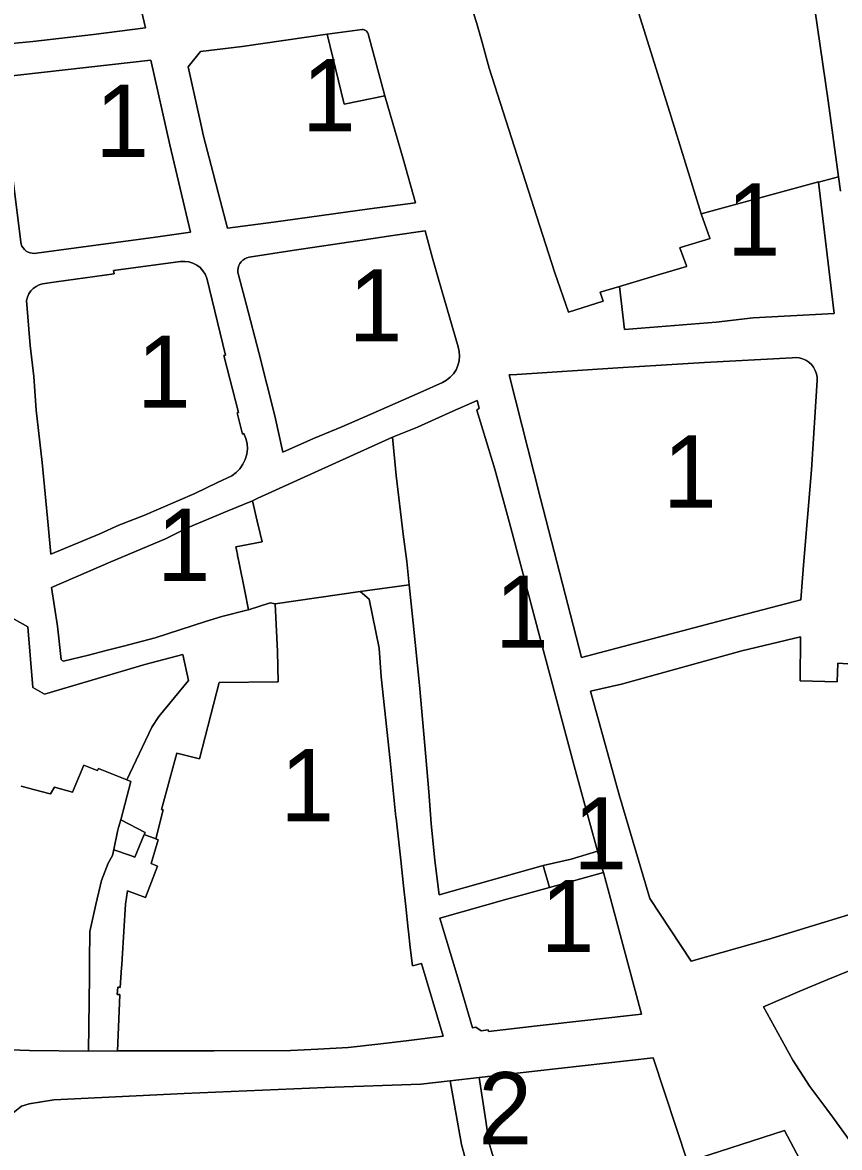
# Model space of a CAD drawing. Extents: x 598968 to 613553, y 4409678 to 4430833.
# Drawn here: x 608032.3 to 608168.2, y 4416080 to 4416267.1 of the extents above; entities that cross this region are included whole.
import ezdxf

# ---------------------------------------------------------------- set-up
doc = ezdxf.new("R2010")
doc.units = 0
for name, color, linetype in [('1', 7, 'Continuous'), ('ZONA 1. NUCLI ANTIC', 7, 'Continuous'), ('ZONA 2. CARRERS DE CASES. Cases de trast', 7, 'Continuous')]:
    doc.layers.add(name, color=color, linetype=linetype)

msp = doc.modelspace()

# ---------------------------------------------------------------- linework, layer by layer
at = {"layer": '1'}
for points in [[(608027.5133, 4416268.2287), (608026.6933, 4416283.6685), (608026.0733, 4416291.9484), (608025.3932, 4416300.2683), (608024.9932, 4416306.4182), (608024.7132, 4416311.1681), (608024.3932, 4416316.5981), (608024.6732, 4416317.238), (608025.2132, 4416317.4581), (608030.5231, 4416315.7882), (608038.313, 4416313.2883), (608042.953, 4416311.7984), (608044.683, 4416303.4636), (608046.433, 4416294.9887), (608048.233, 4416286.3588), (608049.443, 4416280.4589), (608052.733, 4416266.2492), (608044.1131, 4416265.129), (608034.0133, 4416263.9789), (608030.5133, 4416263.6288), (608027.7533, 4416263.5187)], [(608162.2718, 4416281.5809), (608159.1919, 4416281.8608), (608151.252, 4416280.5868), (608150.5865, 4416280.5681), (608150.322, 4416280.5607), (608149.422, 4416280.2907), (608141.8621, 4416278.9106), (608140.9748, 4416278.9934), (608139.6621, 4416278.7205), (608134.6622, 4416277.9605), (608134.8722, 4416277.2705), (608132.2293, 4416276.8197), (608132.2245, 4416276.8179), (608135.3382, 4416266.8385), (608139.9259, 4416252.1354), (608145.1722, 4416235.3212), (608164.6719, 4416240.6514), (608164.6802, 4416240.5821), (608167.999, 4416241.4772), (608166.2927, 4416254.0849)], [(608082.9728, 4416265.1697), (608088.7527, 4416265.9598), (608088.9197, 4416265.9536), (608089.0832, 4416265.9192), (608089.2386, 4416265.8578), (608089.3814, 4416265.7711), (608089.5075, 4416265.6615), (608089.6134, 4416265.5322), (608089.6959, 4416265.3869), (608089.7527, 4416265.2298), (608092.5193, 4416254.922), (608092.5227, 4416254.91), (608095.5927, 4416244.4502), (608097.6432, 4416237.1342), (608090.0228, 4416236.1202), (608080.0329, 4416234.77), (608074.053, 4416233.9199), (608066.393, 4416232.9098), (608064.903, 4416238.6297), (608064.013, 4416242.0696), (608062.413, 4416248.2295), (608061.953, 4416250.2995), (608059.863, 4416259.7494), (608061.8629, 4416262.2794), (608068.833, 4416263.1495)], [(608092.5193, 4416254.922), (608089.7527, 4416265.2298), (608089.6959, 4416265.3869), (608089.6134, 4416265.5322), (608089.5075, 4416265.6615), (608089.3814, 4416265.7711), (608089.2386, 4416265.8578), (608089.0832, 4416265.9192), (608088.9197, 4416265.9536), (608088.7527, 4416265.9598), (608082.9728, 4416265.1697), (608085.7828, 4416253.5599)], [(608056.7931, 4416246.7995), (608060.2531, 4416232.2697), (608054.3931, 4416231.4096), (608034.6234, 4416228.7793), (608034.2642, 4416228.7281), (608033.9014, 4416228.7374), (608033.5453, 4416228.807), (608033.2058, 4416228.9349), (608032.8923, 4416229.1176), (608032.6135, 4416229.3498), (608032.3774, 4416229.6253), (608032.1904, 4416229.9363), (608032.0579, 4416230.2741), (608031.9834, 4416230.6292), (608028.5933, 4416258.0388), (608053.613, 4416260.8392)], [(608077.143, 4416229.19), (608088.3728, 4416230.8702), (608093.8728, 4416231.7003), (608099.2327, 4416232.5004), (608100.4927, 4416227.9405), (608101.4727, 4416224.4205), (608104.7627, 4416213.1707), (608104.9356, 4416212.403), (608104.9844, 4416211.6175), (608104.9077, 4416210.8343), (608104.7075, 4416210.0732), (608104.3889, 4416209.3538), (608103.96, 4416208.694), (608103.4316, 4416208.1107), (608102.8174, 4416207.6187), (608102.1328, 4416207.2307), (608098.4428, 4416205.5907), (608090.0829, 4416201.9306), (608085.393, 4416199.8705), (608080.673, 4416197.9105), (608075.6031, 4416195.6704), (608074.2531, 4416201.6803), (608071.585, 4416212.2381), (608069.5431, 4416220.1), (608068.1831, 4416225.1799), (608068.1143, 4416225.5564), (608068.1069, 4416225.939), (608068.1611, 4416226.3179), (608068.2755, 4416226.6831), (608068.4472, 4416227.0251), (608068.6717, 4416227.3351), (608068.943, 4416227.605), (608069.2543, 4416227.8277), (608069.5973, 4416227.9975), (608069.9631, 4416228.1099)], [(608034.5735, 4416202.6196), (608034.1934, 4416208.2395), (608033.5834, 4416213.4095), (608032.9434, 4416220.8994), (608033.0999, 4416221.4609), (608033.3465, 4416221.989), (608033.6766, 4416222.4694), (608034.0812, 4416222.8892), (608034.5492, 4416223.2366), (608035.068, 4416223.5025), (608035.6234, 4416223.6794), (608037.9133, 4416223.9694), (608047.5132, 4416225.3296), (608047.4232, 4416225.8695), (608058.5731, 4416227.3597), (608059.2709, 4416227.392), (608059.9637, 4416227.3036), (608060.631, 4416227.0971), (608061.2527, 4416226.7786), (608061.8102, 4416226.3577), (608062.2868, 4416225.8471), (608062.6682, 4416225.2619), (608062.9431, 4416224.6198), (608066.0531, 4416211.8), (608065.7486, 4416211.7295), (608068.2332, 4416202.2402), (608067.9861, 4416202.179), (608068.8532, 4416198.6803), (608069.1231, 4416198.7905), (608069.4502, 4416197.96), (608069.6378, 4416197.0874), (608069.6811, 4416196.1959), (608069.5788, 4416195.3092), (608069.3337, 4416194.4509), (608068.9523, 4416193.6439), (608068.4447, 4416192.9097), (608067.8245, 4416192.2678), (608067.1081, 4416191.7353), (608064.7431, 4416190.5903), (608060.9432, 4416188.7802), (608052.4433, 4416185.1401), (608048.3334, 4416183.5101), (608045.1634, 4416182.08), (608036.9935, 4416178.7099), (608036.5635, 4416183.5199), (608035.5335, 4416193.9597)], [(608118.4326, 4416187.9444), (608113.2326, 4416208.5009), (608114.4826, 4416208.5909), (608131.2724, 4416209.7012), (608145.7322, 4416210.5615), (608160.3019, 4416211.3417), (608160.8833, 4416211.3828), (608161.4637, 4416211.3295), (608162.0279, 4416211.183), (608162.5608, 4416210.9473), (608163.0487, 4416210.6285), (608163.4787, 4416210.2349), (608163.8394, 4416209.7771), (608164.1214, 4416209.267), (608164.3171, 4416208.718), (608164.4216, 4416208.1446), (608164.432, 4416207.5618), (608163.4921, 4416192.742), (608162.1622, 4416176.8622), (608161.7322, 4416171.0922), (608147.9124, 4416167.502), (608125.2326, 4416161.5117)], [(608096.5729, 4416173.571), (608096.1829, 4416177.471), (608095.6176, 4416182.0478), (608094.4129, 4416191.8008), (608093.8029, 4416198.1507), (608071.4232, 4416188.0304), (608070.5532, 4416187.5904), (608071.3382, 4416184.1705), (608071.8232, 4416182.1205), (608072.1232, 4416180.7505), (608067.7818, 4416179.9421), (608067.8723, 4416179.4391), (608068.0321, 4416178.6296), (608068.0671, 4416178.4522), (608068.2634, 4416177.4576), (608069.2495, 4416172.5409), (608069.8698, 4416169.4478), (608073.5032, 4416170.5807), (608074.3332, 4416170.4207), (608088.453, 4416172.4809)], [(608052.5035, 4416132.0508), (608052.6635, 4416132.4108), (608048.6435, 4416134.5207), (608048.6247, 4416134.5318), (608048.2691, 4416133.2073), (608048.09, 4416132.5402), (608047.4966, 4416129.5623), (608047.489, 4416129.5241), (608050.263, 4416128.5498), (608050.9435, 4416128.3108), (608051.7235, 4416130.1808)], [(608054.8735, 4416131.1708), (608054.4526, 4416131.3271), (608052.5035, 4416132.0508), (608051.7235, 4416130.1808), (608050.9435, 4416128.3108), (608050.263, 4416128.5498), (608047.489, 4416129.5241), (608047.4966, 4416129.5623), (608047.2636, 4416128.5807), (608046.5336, 4416127.3207), (608045.4036, 4416124.4207), (608044.505, 4416120.415), (608043.5036, 4416115.9508), (608043.449, 4416110.9897), (608043.4162, 4416108.4763), (608043.2537, 4416096.041), (608048.0831, 4416096.091), (608048.0937, 4416096.0911), (608048.3607, 4416102.6651), (608048.4731, 4416105.4297), (608048.2085, 4416105.4431), (608048.0536, 4416105.451), (608048.1237, 4416106.6517), (608048.2429, 4416106.646), (608048.5536, 4416106.631), (608048.7589, 4416109.9424), (608048.7819, 4416110.3133), (608048.8499, 4416111.4099), (608049.4136, 4416120.5009), (608049.7356, 4416122.7168), (608052.7635, 4416121.6109), (608054.7338, 4416126.8117), (608053.6935, 4416127.2208)]]:
    msp.add_lwpolyline(points, close=True, dxfattribs=at)
for points in [[(608107.3325, 4416268.5301), (608107.7825, 4416267.1201), (608108.6515, 4416264.0155), (608109.9125, 4416259.5102), (608118.2425, 4416233.4007), (608120.8225, 4416225.5108), (608123.1024, 4416218.9467), (608128.8659, 4416220.7874), (608128.3324, 4416222.271), (608131.5624, 4416223.2011), (608131.5683, 4416223.2028), (608131.5666, 4416223.2169), (608138.4123, 4416225.2412), (608142.7361, 4416226.5194), (608142.7422, 4416226.5212), (608142.6902, 4416226.6651), (608141.6122, 4416229.6512), (608141.7382, 4416229.6904), (608146.6322, 4416231.2112), (608146.6215, 4416231.2412), (608145.1722, 4416235.3212), (608139.9259, 4416252.1354), (608135.3382, 4416266.8385), (608132.2245, 4416276.8179)], [(608168.3219, 4416239.0915), (608167.999, 4416241.4772), (608164.6802, 4416240.5821), (608167.282, 4416218.7417), (608153.8121, 4416218.0015), (608147.6322, 4416217.2814), (608132.4116, 4416216.0491), (608131.5683, 4416223.2028), (608131.5624, 4416223.2011), (608128.3324, 4416222.271), (608128.8659, 4416220.7874), (608123.1024, 4416218.9467), (608120.8225, 4416225.5108), (608118.2425, 4416233.4007), (608109.9125, 4416259.5102), (608108.6515, 4416264.0155), (608107.7825, 4416267.1201), (608107.3325, 4416268.5301)], [(608029.4938, 4416168.6388), (608033.1736, 4416166.61), (608033.9836, 4416156.5401), (608035.9436, 4416155.4302), (608052.6434, 4416160.3304), (608058.9533, 4416162.0005), (608059.9005, 4416157.6773), (608057.5433, 4416154.8406), (608054.9734, 4416151.7106), (608053.7834, 4416149.9406), (608049.6237, 4416141.1411), (608050.3235, 4416140.8606), (608048.6247, 4416134.5318), (608048.6435, 4416134.5207), (608052.6635, 4416132.4108), (608052.5035, 4416132.0508), (608054.4526, 4416131.3271), (608054.4535, 4416131.3308), (608055.6634, 4416136.1608), (608055.3834, 4416136.2208), (608057.9334, 4416145.6107), (608061.6995, 4416144.6538), (608064.9941, 4416157.3607), (608074.8132, 4416157.4709), (608074.6832, 4416162.5108), (608074.3332, 4416170.4207), (608073.5032, 4416170.5807), (608069.8698, 4416169.4478), (608069.8433, 4416169.4506), (608065.4332, 4416168.3406), (608062.7232, 4416167.4805), (608054.3634, 4416164.7704), (608049.0934, 4416163.3803), (608046.2095, 4416162.687), (608043.2635, 4416161.9102), (608039.1135, 4416160.8902), (608038.9035, 4416160.9902), (608038.7335, 4416161.2002), (608038.0835, 4416166.7201), (608037.1335, 4416173.13), (608046.9734, 4416177.4301), (608056.0533, 4416181.2502), (608059.8332, 4416183.1403), (608066.3131, 4416185.8504), (608070.5532, 4416187.5904), (608071.4232, 4416188.0304), (608093.8029, 4416198.1507), (608097.9528, 4416199.8108), (608103.8828, 4416202.4608), (608107.9027, 4416204.2709), (608108.2427, 4416202.9709), (608107.8658, 4416202.6679), (608110.8327, 4416192.8111), (608113.2727, 4416183.9012), (608115.3327, 4416176.2113), (608118.2727, 4416165.1015), (608121.1527, 4416154.3217), (608124.0327, 4416143.4719), (608127.8627, 4416129.5321), (608127.9333, 4416129.273), (608128.661, 4416126.6038), (608128.8962, 4416125.7386), (608130.4727, 4416119.9523), (608135.2527, 4416102.1726), (608117.8729, 4416100.2323), (608109.813, 4416099.3022), (608109.713, 4416099.5622), (608108.593, 4416099.3922), (608107.653, 4416099.9921), (608107.1131, 4416099.8821), (608104.8531, 4416107.682), (608101.6931, 4416118.1618), (608112.8229, 4416121.332), (608119.9428, 4416123.2521), (608118.8758, 4416126.8987), (608101.603, 4416122.0118), (608100.873, 4416127.7517), (608100.273, 4416133.9116), (608099.873, 4416139.1615), (608099.353, 4416145.0014), (608098.303, 4416156.9013), (608097.2329, 4416167.2611), (608096.5729, 4416173.571), (608088.453, 4416172.4809), (608089.953, 4416171.231), (608091.613, 4416163.0511), (608091.913, 4416158.3012), (608093.4331, 4416144.3513), (608094.3976, 4416134.9483), (608094.4131, 4416134.7761), (608095.2031, 4416127.8016), (608095.6431, 4416123.5216), (608096.0231, 4416120.0917), (608096.4431, 4416116.2917), (608096.481, 4416115.9535), (608096.7831, 4416113.2618), (608097.1231, 4416110.2318), (608098.6331, 4416110.5918), (608102.2731, 4416098.5021), (608096.5632, 4416097.802), (608091.8782, 4416097.2415), (608086.4533, 4416096.6618), (608081.3834, 4416096.3717), (608076.8334, 4416096.1616), (608064.1435, 4416096.0714), (608058.4135, 4416096.0613), (608048.0937, 4416096.0911), (608048.0831, 4416096.091), (608043.2537, 4416096.041), (608033.4538, 4416096.1609), (608028.6876, 4416096.2937)], [(608173.1222, 4416119.7631), (608156.2224, 4416114.5928), (608143.5004, 4416111.0235), (608136.6126, 4416121.4424), (608131.5376, 4416138.6471), (608126.7726, 4416155.9318), (608131.9326, 4416157.0519), (608151.9223, 4416162.6222), (608161.6722, 4416164.9223), (608161.6022, 4416157.6024), (608167.795, 4416157.482), (608167.8621, 4416160.5525), (608178.812, 4416159.8527)], [(608028.6876, 4416096.2937), (608033.4538, 4416096.1609), (608043.2537, 4416096.041), (608043.4162, 4416108.4763), (608043.449, 4416110.9897), (608043.5036, 4416115.9508), (608044.505, 4416120.415), (608045.4036, 4416124.4207), (608046.5336, 4416127.3207), (608047.2636, 4416128.5807), (608047.4966, 4416129.5623), (608048.09, 4416132.5402), (608048.2691, 4416133.2073), (608048.6247, 4416134.5318), (608050.3235, 4416140.8606), (608049.6237, 4416141.1411), (608044.9435, 4416143.0205), (608044.7635, 4416142.6905), (608044.1537, 4416142.9339), (608042.4836, 4416143.6005), (608040.6236, 4416139.0905), (608037.6136, 4416139.9204), (608036.9236, 4416138.8304), (608036.9136, 4416138.8147), (608034.1402, 4416139.555), (608032.0837, 4416140.0903)], [(608170.0624, 4416080.9135), (608166.9984, 4416085.0934), (608166.0684, 4416086.3833), (608163.2484, 4416090.1332), (608160.4124, 4416094.5531), (608155.5125, 4416103.4129), (608161.5524, 4416105.993), (608166.2023, 4416107.9631), (608171.5423, 4416110.1231)], [(607925.6553, 4416035.0097), (608009.5141, 4416102.6604), (608029.3439, 4416084.6409), (608032.1339, 4416086.891), (608033.3789, 4416087.291), (608037.5115, 4416087.9368), (608059.2003, 4416088.9888), (608082.6384, 4416089.9718), (608098.5432, 4416090.5421), (608103.3862, 4416091.0948), (608108.2581, 4416091.6507), (608117.473, 4416092.7024), (608137.1627, 4416094.9227), (608142.8727, 4416077.613), (608159.0125, 4416082.8533), (608162.5225, 4416076.2184)]]:
    msp.add_lwpolyline(points, dxfattribs=at)
at = {"layer": 'ZONA 1. NUCLI ANTIC'}
for points in [[(608030.5133, 4416263.6288), (608034.0133, 4416263.9789), (608044.1131, 4416265.129), (608052.733, 4416266.2492), (608049.443, 4416280.4589), (608048.233, 4416286.3588), (608046.433, 4416294.9887), (608044.683, 4416303.4636), (608042.953, 4416311.7984), (608038.313, 4416313.2883), (608030.5231, 4416315.7882), (608025.2132, 4416317.4581), (608024.6732, 4416317.238), (608024.3932, 4416316.5981), (608024.7132, 4416311.1681), (608024.9932, 4416306.4182), (608025.3932, 4416300.2683), (608026.0733, 4416291.9484), (608026.6933, 4416283.6685), (608027.5133, 4416268.2287), (608027.7533, 4416263.5187)], [(608092.5193, 4416254.922), (608085.7828, 4416253.5599), (608082.9728, 4416265.1697), (608068.833, 4416263.1495), (608061.8629, 4416262.2794), (608059.863, 4416259.7494), (608061.953, 4416250.2995), (608062.413, 4416248.2295), (608064.013, 4416242.0696), (608064.903, 4416238.6297), (608066.393, 4416232.9098), (608074.053, 4416233.9199), (608080.0329, 4416234.77), (608090.0228, 4416236.1202), (608097.6432, 4416237.1342), (608095.5927, 4416244.4502), (608092.5227, 4416254.91)], [(608034.6234, 4416228.7793), (608054.3931, 4416231.4096), (608060.2531, 4416232.2697), (608056.7931, 4416246.7995), (608053.613, 4416260.8392), (608028.5933, 4416258.0388), (608031.9834, 4416230.6292), (608032.0579, 4416230.2741), (608032.1904, 4416229.9363), (608032.3774, 4416229.6253), (608032.6135, 4416229.3498), (608032.8923, 4416229.1176), (608033.2058, 4416228.9349), (608033.5453, 4416228.807), (608033.9014, 4416228.7374), (608034.2642, 4416228.7281)], [(608164.6802, 4416240.5821), (608164.6719, 4416240.6514), (608145.1722, 4416235.3212), (608146.6215, 4416231.2412), (608146.6322, 4416231.2112), (608141.7382, 4416229.6904), (608141.6122, 4416229.6512), (608142.6902, 4416226.6651), (608142.7422, 4416226.5212), (608142.7361, 4416226.5194), (608138.4123, 4416225.2412), (608131.5666, 4416223.2169), (608131.5683, 4416223.2028), (608132.4116, 4416216.0491), (608147.6322, 4416217.2814), (608153.8121, 4416218.0015), (608167.282, 4416218.7417)], [(608080.673, 4416197.9105), (608085.393, 4416199.8705), (608090.0829, 4416201.9306), (608098.4428, 4416205.5907), (608102.1328, 4416207.2307), (608102.8174, 4416207.6187), (608103.4316, 4416208.1107), (608103.96, 4416208.694), (608104.3889, 4416209.3538), (608104.7075, 4416210.0732), (608104.9077, 4416210.8343), (608104.9844, 4416211.6175), (608104.9356, 4416212.403), (608104.7627, 4416213.1707), (608101.4727, 4416224.4205), (608100.4927, 4416227.9405), (608099.2327, 4416232.5004), (608093.8728, 4416231.7003), (608088.3728, 4416230.8702), (608077.143, 4416229.19), (608069.9631, 4416228.1099), (608069.5973, 4416227.9975), (608069.2543, 4416227.8277), (608068.943, 4416227.605), (608068.6717, 4416227.3351), (608068.4472, 4416227.0251), (608068.2755, 4416226.6831), (608068.1611, 4416226.3179), (608068.1069, 4416225.939), (608068.1143, 4416225.5564), (608068.1831, 4416225.1799), (608069.5431, 4416220.1), (608071.585, 4416212.2381), (608074.2531, 4416201.6803), (608075.6031, 4416195.6704)], [(608067.9861, 4416202.179), (608068.2332, 4416202.2402), (608065.7486, 4416211.7295), (608066.0531, 4416211.8), (608062.9431, 4416224.6198), (608062.6682, 4416225.2619), (608062.2868, 4416225.8471), (608061.8102, 4416226.3577), (608061.2527, 4416226.7786), (608060.631, 4416227.0971), (608059.9637, 4416227.3036), (608059.2709, 4416227.392), (608058.5731, 4416227.3597), (608047.4232, 4416225.8695), (608047.5132, 4416225.3296), (608037.9133, 4416223.9694), (608035.6234, 4416223.6794), (608035.068, 4416223.5025), (608034.5492, 4416223.2366), (608034.0812, 4416222.8892), (608033.6766, 4416222.4694), (608033.3465, 4416221.989), (608033.0999, 4416221.4609), (608032.9434, 4416220.8994), (608033.5834, 4416213.4095), (608034.1934, 4416208.2395), (608034.5735, 4416202.6196), (608035.5335, 4416193.9597), (608036.5635, 4416183.5199), (608036.9935, 4416178.7099), (608045.1634, 4416182.08), (608048.3334, 4416183.5101), (608052.4433, 4416185.1401), (608060.9432, 4416188.7802), (608064.7431, 4416190.5903), (608067.1081, 4416191.7353), (608067.8245, 4416192.2678), (608068.4447, 4416192.9097), (608068.9523, 4416193.6439), (608069.3337, 4416194.4509), (608069.5788, 4416195.3092), (608069.6811, 4416196.1959), (608069.6378, 4416197.0874), (608069.4502, 4416197.96), (608069.1231, 4416198.7905), (608068.8532, 4416198.6803)], [(608147.9124, 4416167.502), (608161.7322, 4416171.0922), (608162.1622, 4416176.8622), (608163.4921, 4416192.742), (608164.432, 4416207.5618), (608164.4216, 4416208.1446), (608164.3171, 4416208.718), (608164.1214, 4416209.267), (608163.8394, 4416209.7771), (608163.4787, 4416210.2349), (608163.0487, 4416210.6285), (608162.5608, 4416210.9473), (608162.0279, 4416211.183), (608161.4637, 4416211.3295), (608160.8833, 4416211.3828), (608160.3019, 4416211.3417), (608145.7322, 4416210.5615), (608131.2724, 4416209.7012), (608114.4826, 4416208.5909), (608113.2326, 4416208.5009), (608118.4326, 4416187.9444), (608125.2326, 4416161.5117)], [(608127.9333, 4416129.273), (608127.8627, 4416129.5321), (608124.0327, 4416143.4719), (608121.1527, 4416154.3217), (608118.2727, 4416165.1015), (608115.3327, 4416176.2113), (608113.2727, 4416183.9012), (608110.8327, 4416192.8111), (608107.8658, 4416202.6679), (608108.2427, 4416202.9709), (608107.9027, 4416204.2709), (608103.8828, 4416202.4608), (608097.9528, 4416199.8108), (608093.8029, 4416198.1507), (608094.4129, 4416191.8008), (608095.6176, 4416182.0478), (608096.1829, 4416177.471), (608096.5729, 4416173.571), (608097.2329, 4416167.2611), (608098.303, 4416156.9013), (608099.353, 4416145.0014), (608099.873, 4416139.1615), (608100.273, 4416133.9116), (608100.873, 4416127.7517), (608101.603, 4416122.0118), (608118.8758, 4416126.8987), (608123.5336, 4416127.9394)], [(608069.8698, 4416169.4478), (608069.2495, 4416172.5409), (608068.2634, 4416177.4576), (608068.0671, 4416178.4522), (608068.0321, 4416178.6296), (608067.8723, 4416179.4391), (608067.7818, 4416179.9421), (608072.1232, 4416180.7505), (608071.8232, 4416182.1205), (608071.3382, 4416184.1705), (608070.5532, 4416187.5904), (608066.3131, 4416185.8504), (608059.8332, 4416183.1403), (608056.0533, 4416181.2502), (608046.9734, 4416177.4301), (608037.1335, 4416173.13), (608038.0835, 4416166.7201), (608038.7335, 4416161.2002), (608038.9035, 4416160.9902), (608039.1135, 4416160.8902), (608043.2635, 4416161.9102), (608046.2095, 4416162.687), (608049.0934, 4416163.3803), (608054.3634, 4416164.7704), (608062.7232, 4416167.4805), (608065.4332, 4416168.3406), (608069.8433, 4416169.4506)], [(608048.0937, 4416096.0911), (608058.4135, 4416096.0613), (608064.1435, 4416096.0714), (608076.8334, 4416096.1616), (608081.3834, 4416096.3717), (608086.4533, 4416096.6618), (608091.8782, 4416097.2415), (608096.5632, 4416097.802), (608102.2731, 4416098.5021), (608098.6331, 4416110.5918), (608097.1231, 4416110.2318), (608096.7831, 4416113.2618), (608096.481, 4416115.9535), (608096.4431, 4416116.2917), (608096.0231, 4416120.0917), (608095.6431, 4416123.5216), (608095.2031, 4416127.8016), (608094.4131, 4416134.7761), (608094.3976, 4416134.9483), (608093.4331, 4416144.3513), (608091.913, 4416158.3012), (608091.613, 4416163.0511), (608089.953, 4416171.231), (608088.453, 4416172.4809), (608074.3332, 4416170.4207), (608074.6832, 4416162.5108), (608074.8132, 4416157.4709), (608064.9941, 4416157.3607), (608061.6995, 4416144.6538), (608057.9334, 4416145.6107), (608055.3834, 4416136.2208), (608055.6634, 4416136.1608), (608054.4535, 4416131.3308), (608054.4526, 4416131.3271), (608054.8735, 4416131.1708), (608053.6935, 4416127.2208), (608054.7338, 4416126.8117), (608052.7635, 4416121.6109), (608049.7356, 4416122.7168), (608049.4136, 4416120.5009), (608048.8499, 4416111.4099), (608048.7819, 4416110.3133), (608048.7589, 4416109.9424), (608048.5536, 4416106.631), (608048.2429, 4416106.646), (608048.1237, 4416106.6517), (608048.0536, 4416105.451), (608048.2085, 4416105.4431), (608048.4731, 4416105.4297), (608048.3607, 4416102.6651)], [(608128.8962, 4416125.7386), (608128.661, 4416126.6038), (608127.9333, 4416129.273), (608123.5336, 4416127.9394), (608118.8758, 4416126.8987), (608119.9428, 4416123.2521)], [(608119.9428, 4416123.2521), (608112.8229, 4416121.332), (608101.6931, 4416118.1618), (608104.8531, 4416107.682), (608107.1131, 4416099.8821), (608107.653, 4416099.9921), (608108.593, 4416099.3922), (608109.713, 4416099.5622), (608109.813, 4416099.3022), (608117.8729, 4416100.2323), (608135.2527, 4416102.1726), (608130.4727, 4416119.9523), (608128.8962, 4416125.7386)]]:
    msp.add_lwpolyline(points, close=True, dxfattribs=at)
for points in [[(608177.6116, 4416284.0411), (608162.2718, 4416281.5809), (608166.2927, 4416254.0849), (608167.999, 4416241.4772), (608168.3219, 4416239.0915)], [(608032.0837, 4416140.0903), (608034.1402, 4416139.555), (608036.9136, 4416138.8147), (608036.9236, 4416138.8304), (608037.6136, 4416139.9204), (608040.6236, 4416139.0905), (608042.4836, 4416143.6005), (608044.1537, 4416142.9339), (608044.7635, 4416142.6905), (608044.9435, 4416143.0205), (608049.6237, 4416141.1411), (608053.7834, 4416149.9406), (608054.9734, 4416151.7106), (608057.5433, 4416154.8406), (608059.9005, 4416157.6773), (608058.9533, 4416162.0005), (608052.6434, 4416160.3304), (608035.9436, 4416155.4302), (608033.9836, 4416156.5401), (608033.1736, 4416166.61), (608029.4938, 4416168.6388)], [(608178.812, 4416159.8527), (608167.8621, 4416160.5525), (608167.795, 4416157.482), (608161.6022, 4416157.6024), (608161.6722, 4416164.9223), (608151.9223, 4416162.6222), (608131.9326, 4416157.0519), (608126.7726, 4416155.9318), (608131.5376, 4416138.6471), (608136.6126, 4416121.4424), (608143.5004, 4416111.0235), (608156.2224, 4416114.5928), (608173.1222, 4416119.7631)], [(608171.5423, 4416110.1231), (608166.2023, 4416107.9631), (608161.5524, 4416105.993), (608155.5125, 4416103.4129), (608160.4124, 4416094.5531), (608163.2484, 4416090.1332), (608166.0684, 4416086.3833), (608166.9984, 4416085.0934), (608170.0624, 4416080.9135)]]:
    msp.add_lwpolyline(points, dxfattribs=at)
at = {"layer": 'ZONA 2. CARRERS DE CASES. Cases de trast'}
for points in [[(608107.718, 4416071.5771), (608105.3031, 4416080.5123), (608103.3862, 4416091.0948), (608098.5432, 4416090.5421), (608082.6384, 4416089.9718), (608059.2003, 4416088.9888), (608037.5115, 4416087.9368), (608033.3789, 4416087.291), (608032.1339, 4416086.891), (608029.3439, 4416084.6409), (608009.5141, 4416102.6604), (607925.6553, 4416035.0097)], [(608162.5225, 4416076.2184), (608159.0125, 4416082.8533), (608142.8727, 4416077.613), (608137.1627, 4416094.9227), (608117.473, 4416092.7024), (608108.2581, 4416091.6507), (608109.3248, 4416084.4423), (608109.8531, 4416080.8724), (608112.0714, 4416073.4108)]]:
    msp.add_lwpolyline(points, dxfattribs=at)
msp.add_lwpolyline([(608112.8231, 4416070.8826), (608112.0714, 4416073.4108), (608109.8531, 4416080.8724), (608109.3248, 4416084.4423), (608108.2581, 4416091.6507), (608103.3862, 4416091.0948), (608105.3031, 4416080.5123), (608107.718, 4416071.5771), (608108.302, 4416069.4164)], close=True, dxfattribs=at)

# ---------------------------------------------------------------- texts
at = {"layer": 'ZONA 1. NUCLI ANTIC'}
for p in [(608078.7531, 4416249.0398), (608044.4232, 4416244.7836), (608149.4243, 4416228.3503), (608086.5457, 4416214.0854), (608051.3122, 4416203.051), (608138.8323, 4416186.4473), (608054.6284, 4416174.2403), (608110.8681, 4416163.1414), (608075.1634, 4416134.2711), (608123.886, 4416126.2626), (608118.4729, 4416112.5204)]:
    msp.add_text('1', height=12, dxfattribs=at).set_placement(p)
at = {"layer": 'ZONA 2. CARRERS DE CASES. Cases de trast'}
msp.add_text('2', height=12, dxfattribs=at).set_placement((608108.1046, 4416080.5336))

doc.saveas('drawing.dxf')
